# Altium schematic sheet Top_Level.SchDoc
size A4; Organization: Q-Tech Design; Address1: Da Nang City; Address2: Viet Nam; DocumentNumber: 1; SheetNumber: 1; SheetTotal: 7
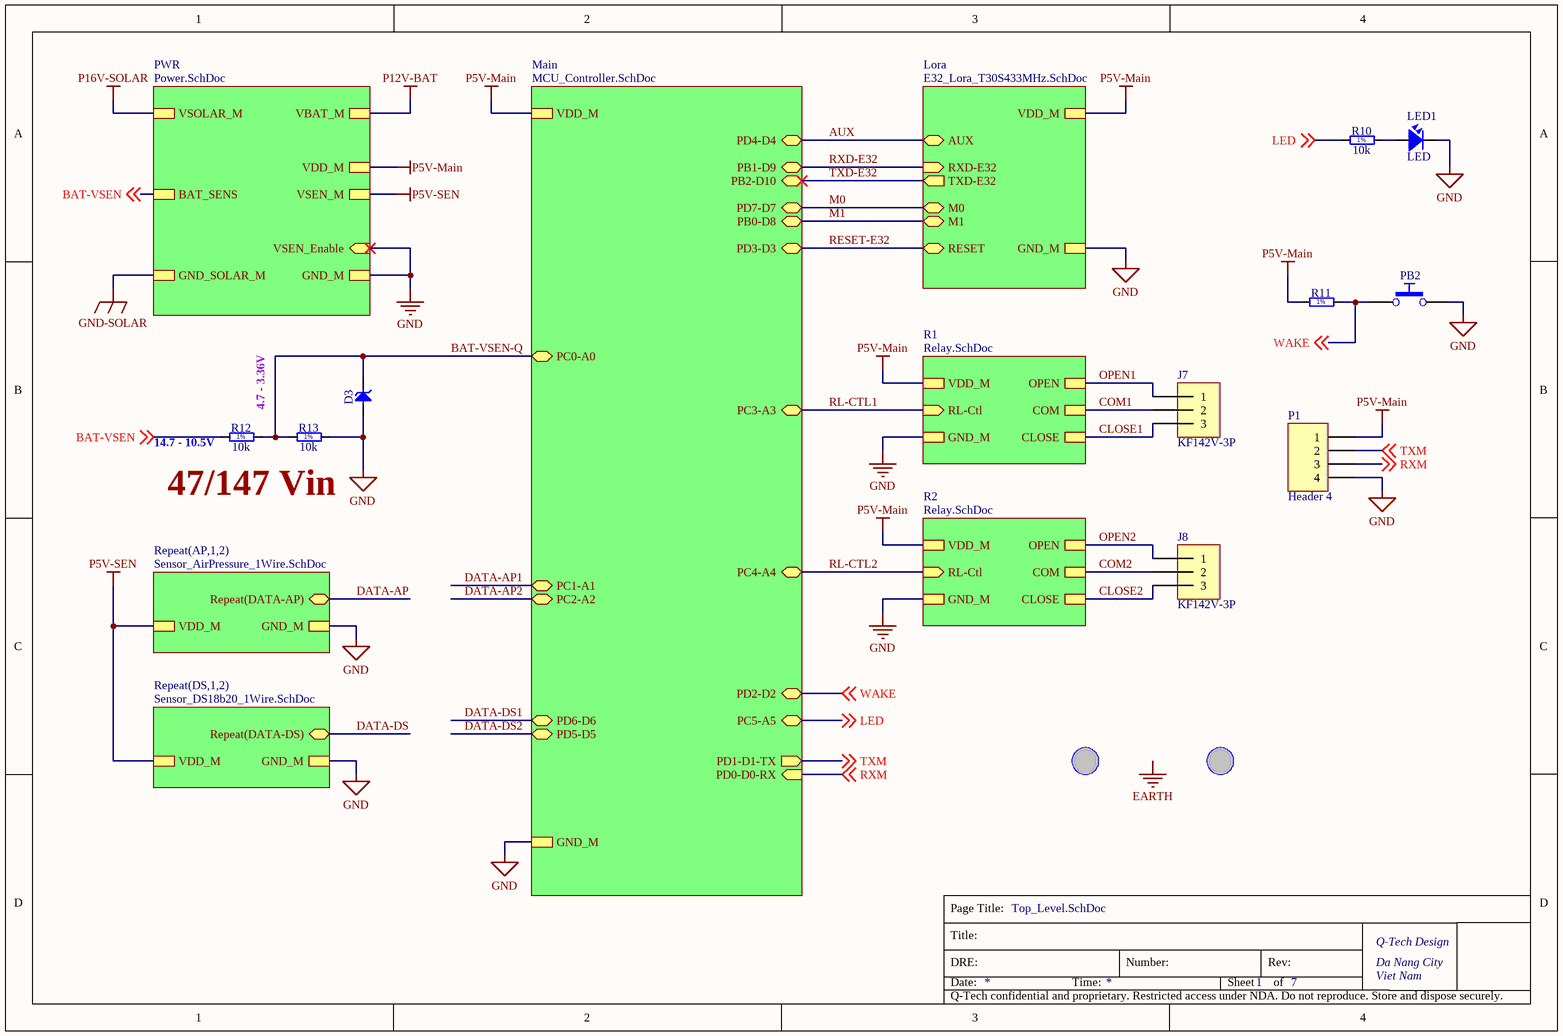
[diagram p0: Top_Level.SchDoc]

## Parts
(Parts that share a designator on the sheet are numbered #1, #2 ... from top to bottom, then left to right.)
D3  BZV55-B5V1  [DIOMELF3515N]  (value not drawn)
HOLE#1  HOLE  [HOLE M3]  (value not drawn)
HOLE#2  HOLE  [HOLE M3]  (value not drawn)
J7  KF142V-3P  [CON KF142V-3P-5.08]
J8  KF142V-3P  [CON KF142V-3P-5.08]
LED1  LED  [L-0805]
P1  Header 4  [HDR1X4]
PB2  Push Button  [PB_TYCO_FSMSM]  (value not drawn)
R10  10k  [RESC1608X55N]
R11  10k  [RESC1608X55N]  (value not drawn)
R12  10k  [RESC1608X55N]
R13  10k  [RESC1608X55N]

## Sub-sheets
Lora = E32_Lora_T30S433MHz.SchDoc: M0 (bidir), M1 (bidir), RESET (bidir), AUX (bidir), GND_M, VDD_M, RXD-E32 (in), TXD-E32 (out)
Main = MCU_Controller.SchDoc: PB1-D9 (bidir), PB2-D10 (bidir), GND_M, PC3-A3 (bidir), PB0-D8 (bidir), PD6-D6 (bidir), PD2-D2 (bidir), PC4-A4 (bidir), PD4-D4 (bidir), PC5-A5 (bidir), PC2-A2 (bidir), PD0-D0-RX (in), PD3-D3 (bidir), PC1-A1 (bidir), PD7-D7 (bidir), VDD_M, PD5-D5 (bidir), PC0-A0 (bidir), PD1-D1-TX (out)
PWR = Power.SchDoc: VSOLAR_M, VSEN_Enable (in), BAT_SENS, VSEN_M, GND_SOLAR_M, VBAT_M, GND_M, VDD_M
R1 = Relay.SchDoc: OPEN, GND_M, CLOSE, RL-Ctl (in), VDD_M, COM
R2 = Relay.SchDoc: OPEN, GND_M, CLOSE, RL-Ctl (in), VDD_M, COM
Repeat(AP,1,2) = Sensor_AirPressure_1Wire.SchDoc: VDD_M, GND_M, Repeat(DATA-AP) (bidir)
Repeat(DS,1,2) = Sensor_DS18b20_1Wire.SchDoc: GND_M, Repeat(DATA-DS) (bidir), VDD_M

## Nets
GND: D3.2(A) LED1.2 P1.4 PB2.2 R13.2 ; sheet Main/GND_M, sheet Lora/GND_M, sheet PWR/VSEN_Enable, sheet PWR/GND_M, sheet Repeat(AP,1,2)/GND_M, sheet Repeat(DS,1,2)/GND_M, sheet R1/GND_M, sheet R2/GND_M
P5V-Main: P1.1 R11.1 ; sheet Main/VDD_M, sheet Lora/VDD_M, sheet PWR/VDD_M, sheet R1/VDD_M, sheet R2/VDD_M
P5V-SEN: sheet PWR/VSEN_M, sheet Repeat(AP,1,2)/VDD_M, sheet Repeat(DS,1,2)/VDD_M
AUX: sheet Main/PD4-D4, sheet Lora/AUX
BAT-VSEN: R12.1 ; off-sheet BAT-VSEN, sheet PWR/BAT_SENS
BAT-VSEN-Q: D3.1(C) R12.2 R13.1 ; sheet Main/PC0-A0
CLOSE1: J7.3 ; sheet R1/CLOSE
CLOSE2: J8.3 ; sheet R2/CLOSE
COM1: J7.2 ; sheet R1/COM
COM2: J8.2 ; sheet R2/COM
LED: R10.1 ; off-sheet LED, sheet Main/PC5-A5
M0: sheet Main/PD7-D7, sheet Lora/M0
M1: sheet Main/PB0-D8, sheet Lora/M1
OPEN1: J7.1 ; sheet R1/OPEN
OPEN2: J8.1 ; sheet R2/OPEN
RESET-E32: sheet Main/PD3-D3, sheet Lora/RESET
RL-CTL1: sheet Main/PC3-A3, sheet R1/RL-Ctl
RL-CTL2: sheet Main/PC4-A4, sheet R2/RL-Ctl
RXD-E32: sheet Main/PB1-D9, sheet Lora/RXD-E32
RXM: P1.3 ; off-sheet RXM, sheet Main/PD0-D0-RX
TXD-E32: sheet Main/PB2-D10, sheet Lora/TXD-E32
TXM: P1.2 ; off-sheet TXM, sheet Main/PD1-D1-TX
WAKE: PB2.1 R11.2 ; off-sheet WAKE, sheet Main/PD2-D2
NetLED1_1: LED1.1 R10.2

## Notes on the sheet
- (near R12) 14.7 - 10.5V
- 4.7 - 3.36V
- 47/147 Vin
- Labels drawn without touching a wire or pin: EARTH

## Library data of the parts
D3 = BZV55-B5V1: Zener Diode; Part Description: Voltage Regulator Diode; Manufacturer: NXP SEMICONDUCTORS; Voltage: 5V1; Power: 500mW; Table: Diodes
HOLE#1 HOLE#2 = HOLE M3
J7 J8 = CON KF142V-3P-5.08
LED1 = LED: LED Single colour Green and Red; Value: LED 3 ly Single Colour
P1 = Header 4: Header, 4-Pin
PB2 = PB SPST 1NO-2NO: Push-Button Switch SPDT; Part Description: 12VDC 50mA SPST Tactile  Push-Button Switch; Manufacturer: TYCO ELECTRONICS; Manufacturer Part Number: FSMSM or 1437566-3; Table: Switches
R10 = R0603_200R_1%_0.1W_100PPM: Resistor - 1%; Part Description: General Purpose Thick Film Chip Resistor; Manufacturer: GENERIC; Manufacturer1 Part Number: NRC06F2000TRF; Value: 200; Power: 0.1W; TC: ±100ppm/°C; Table: Resistors SMD
R11 = R0603_10K_1%_0.1W_100PPM: Resistor - 1%; Part Description: General Purpose Thick Film Chip Resistor; Manufacturer: GENERIC; Manufacturer1 Part Number: NRC06F1002TRF; Power: 0.1W; TC: ±100ppm/°C; Table: Resistors SMD
R12 = R0603_2M_1%_0.1W_100PPM: Resistor - 1%; Part Description: General Purpose Thick Film Chip Resistor; Manufacturer: GENERIC; Manufacturer1 Part Number: NRC06F2004TRF; Value: 2M; Power: 0.1W; TC: ±100ppm/°C; Table: Resistors SMD
R13 = R0603_1M_1%_0.1W_100PPM: Resistor - 1%; Part Description: General Purpose Thick Film Chip Resistor; Manufacturer: GENERIC; Manufacturer1 Part Number: NRC06F1004TRF; Value: 1M; Power: 0.1W; TC: ±100ppm/°C; Table: Resistors SMD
